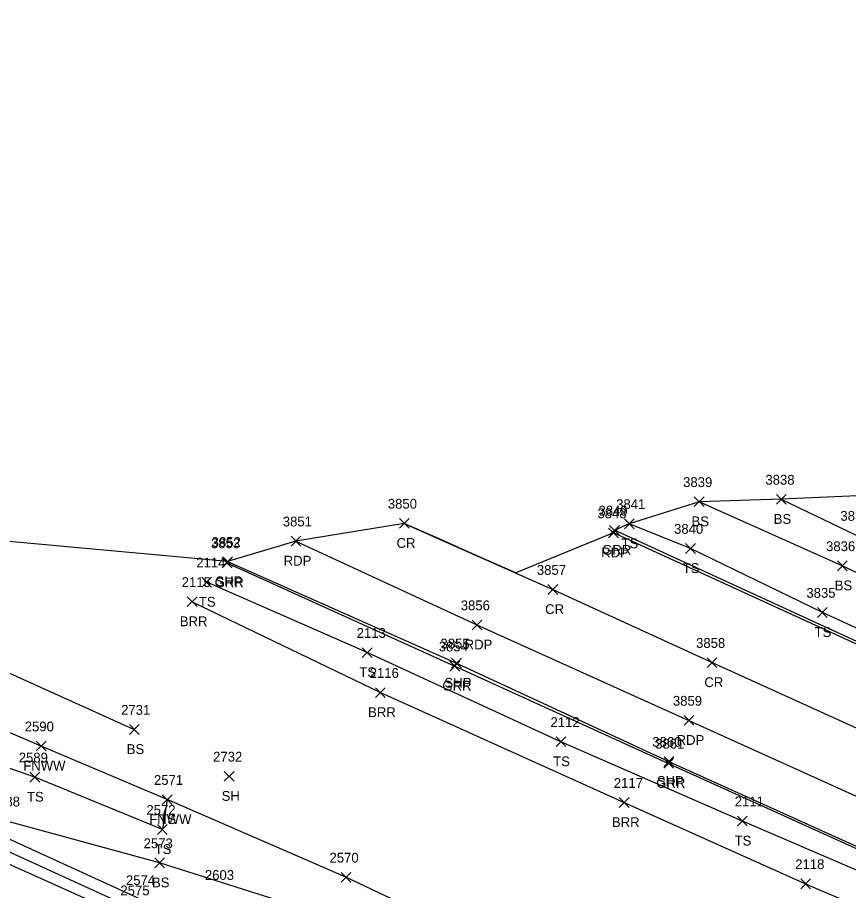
# Model space of a CAD drawing. Extents: x 1599569 to 1610055, y 642560 to 647860.
# Drawn here: x 1601133.3 to 1601302.9, y 647340.3 to 647518.5 of the extents above; entities that cross this region are included whole.
import ezdxf

# ---------------------------------------------------------------- set-up
doc = ezdxf.new("R2010")
doc.units = 0
for name, color, linetype in [('L_A', 7, 'Continuous'), ('L_I', 7, 'Continuous'), ('L_TIC', 7, 'Continuous'), ('LABL', 7, 'Continuous'), ('LELB', 7, 'Continuous'), ('LFNC', 7, 'Continuous'), ('LSOGP', 7, 'Continuous'), ('P_A', 7, 'Continuous'), ('P_I', 7, 'Continuous'), ('P_TIC', 7, 'Continuous'), ('PET', 7, 'Continuous'), ('PRC', 7, 'Continuous'), ('PSP', 7, 'Continuous'), ('R_A', 7, 'Continuous'), ('R_I', 7, 'Continuous'), ('R_TIC', 7, 'Continuous'), ('RGR', 7, 'Continuous'), ('RR', 7, 'Continuous'), ('S_I', 7, 'Continuous')]:
    doc.layers.add(name, color=color, linetype=linetype)

msp = doc.modelspace()

# ---------------------------------------------------------------- linework, layer by layer
at = {"layer": 'L_TIC'}
for points in [[(1601271.46, 647418.68), (1601273.46, 647420.68)], [(1601273.46, 647418.68), (1601271.46, 647420.68)], [(1601288.24, 647419.16), (1601290.24, 647421.16)], [(1601290.24, 647419.16), (1601288.24, 647421.16)], [(1601257.21, 647414.18), (1601259.21, 647416.18)], [(1601259.21, 647414.18), (1601257.21, 647416.18)], [(1601269.69, 647409.14), (1601271.69, 647411.14)], [(1601271.69, 647409.14), (1601269.69, 647411.14)], [(1601300.67, 647405.6), (1601302.67, 647407.6)], [(1601302.67, 647405.6), (1601300.67, 647407.6)], [(1601170.96, 647402.26), (1601172.96, 647404.26)], [(1601172.96, 647402.26), (1601170.96, 647404.26)], [(1601167.99, 647398.27), (1601169.99, 647400.27)], [(1601169.99, 647398.27), (1601167.99, 647400.27)], [(1601296.6, 647396.08), (1601298.6, 647398.08)], [(1601298.6, 647396.08), (1601296.6, 647398.08)], [(1601203.7, 647387.89), (1601205.7, 647389.89)], [(1601205.7, 647387.89), (1601203.7, 647389.89)], [(1601206.41, 647379.73), (1601208.41, 647381.73)], [(1601208.41, 647379.73), (1601206.41, 647381.73)], [(1601156.19, 647372.2), (1601158.19, 647374.2)], [(1601158.19, 647372.2), (1601156.19, 647374.2)], [(1601243.25, 647369.69), (1601245.25, 647371.69)], [(1601245.25, 647369.69), (1601243.25, 647371.69)], [(1601137.18, 647368.81), (1601139.18, 647370.81)], [(1601139.18, 647368.81), (1601137.18, 647370.81)], [(1601175.54, 647362.64), (1601177.54, 647364.64)], [(1601177.54, 647362.64), (1601175.54, 647364.64)], [(1601135.88, 647362.46), (1601137.88, 647364.46)], [(1601137.88, 647362.46), (1601135.88, 647364.46)], [(1601162.89, 647357.89), (1601164.89, 647359.89)], [(1601164.89, 647357.89), (1601162.89, 647359.89)], [(1601162.89, 647357.89), (1601164.89, 647359.89)], [(1601164.89, 647357.89), (1601162.89, 647359.89)], [(1601256.17, 647357.28), (1601258.17, 647359.28)], [(1601258.17, 647357.28), (1601256.17, 647359.28)], [(1601280.28, 647353.51), (1601282.28, 647355.51)], [(1601282.28, 647353.51), (1601280.28, 647355.51)], [(1601161.92, 647351.78), (1601163.92, 647353.78)], [(1601163.92, 647351.78), (1601161.92, 647353.78)], [(1601161.36, 647344.97), (1601163.36, 647346.97)], [(1601163.36, 647344.97), (1601161.36, 647346.97)], [(1601199.38, 647342.03), (1601201.38, 647344.03)], [(1601201.38, 647342.03), (1601199.38, 647344.03)], [(1601293.19, 647340.7), (1601295.19, 647342.7)], [(1601295.19, 647340.7), (1601293.19, 647342.7)]]:
    msp.add_lwpolyline(points, dxfattribs=at)
at = {"layer": 'LABL'}
msp.add_lwpolyline([(1601168.99, 647399.27), (1601207.41, 647380.73), (1601257.17, 647358.28), (1601294.19, 647341.7), (1601346.91, 647319.14), (1601374.73, 647304.92), (1601415.9, 647287.21), (1601447.46, 647269.36), (1601451.82, 647260.74), (1601445.32, 647247.33), (1601438.38, 647230.38)], dxfattribs=at)
at = {"layer": 'LELB'}
for points in [[(1601329.86, 647260.18), (1601292.61, 647278.06), (1601262.72, 647292.4), (1601226.59, 647308.21), (1601190.68, 647323.36), (1601158.75, 647338.43), (1601129.91, 647351.62), (1601096.68, 647366.43), (1601056.58, 647384.54), (1601012.74, 647404.18), (1600965.22, 647426.07), (1600914.49, 647448.77), (1600866.79, 647471.13), (1600821.34, 647492.23), (1600763.72, 647518.52)], [(1601329.08, 647258.95), (1601292.39, 647275.61), (1601261.46, 647289.71), (1601225.27, 647305.87), (1601190.14, 647321.67), (1601157.62, 647336.35), (1601128.98, 647349.36), (1601095.53, 647364.39), (1601055.96, 647382.57), (1601011.7, 647402.22), (1600964.35, 647423.93), (1600913.28, 647446.74), (1600865.78, 647468.67), (1600819.14, 647488.99), (1600762.95, 647515.26)], [(1601277.64, 647306.94), (1601247.91, 647313.96), (1601233.47, 647321.04), (1601196.65, 647335.07), (1601162.36, 647345.97), (1601131.17, 647354.49), (1601097.9, 647368.75), (1601057.17, 647386.63), (1601013.7, 647406.22), (1600966.1, 647427.78), (1600916.08, 647451.44), (1600867.43, 647472.68), (1600824.54, 647496.94)], [(1601163.89, 647358.89), (1601162.92, 647352.78), (1601136.88, 647363.46), (1601101.2, 647375.84), (1601058.43, 647390.08), (1601014.73, 647408.69), (1600966.71, 647430.59), (1600917.74, 647454.04), (1600870.28, 647476.33), (1600824.54, 647496.94)], [(1600923.02, 647485.83), (1600958.02, 647473.82), (1601000.93, 647451.94), (1601046.02, 647433.27), (1601084.8, 647415.84), (1601116.74, 647391.45), (1601157.19, 647373.2)], [(1601404.15, 647367.47), (1601371.11, 647382.8), (1601340.04, 647397.51), (1601304.55, 647412.79), (1601289.24, 647420.16)], [(1601401.43, 647361.74), (1601367.5, 647374.69), (1601335.03, 647390.68), (1601301.67, 647406.6), (1601272.46, 647419.68)], [(1601397.61, 647351.48), (1601365.05, 647366.71), (1601330.24, 647382.11), (1601297.6, 647397.08), (1601270.69, 647410.14), (1601258.21, 647415.18)], [(1601313.74, 647340.53), (1601281.28, 647354.51), (1601244.25, 647370.69), (1601204.7, 647388.89), (1601171.96, 647403.26)]]:
    msp.add_lwpolyline(points, dxfattribs=at)
at = {"layer": 'LFNC'}
msp.add_lwpolyline([(1601438.38, 647230.38), (1601406.08, 647246.23), (1601390.36, 647253.65), (1601325.07, 647284.52), (1601295.93, 647298.24), (1601277.64, 647306.94), (1601251.54, 647319.32), (1601236.24, 647326.06), (1601200.38, 647343.03), (1601163.89, 647358.89), (1601138.18, 647369.81), (1601105.25, 647383.87), (1601061.33, 647402.55), (1601021.95, 647420.15), (1600970.86, 647443.1), (1600923.39, 647465.04), (1600876.08, 647486.37)], dxfattribs=at)
at = {"layer": 'LSOGP'}
msp.add_lwpolyline([(1601329.63, 647421.95), (1601289.24, 647420.17), (1601272.46, 647419.67), (1601258.21, 647415.18), (1601255.18, 647413.85), (1601254.97, 647413.31), (1601235.02, 647405.14), (1601227.44, 647408.51), (1601219.86, 647411.89), (1601212.28, 647415.27), (1601190.18, 647411.64), (1601176.24, 647407.45), (1601084.8, 647415.84), (1601084.8, 647415.85), (1601046.02, 647433.27), (1601000.93, 647451.95), (1600958.02, 647473.82), (1600923.02, 647485.84), (1600876.08, 647486.37), (1600824.54, 647496.94), (1600763.73, 647518.52)], dxfattribs=at)
at = {"layer": 'P_TIC'}
for points in [[(1601211.28, 647414.26), (1601213.28, 647416.26)], [(1601213.28, 647414.26), (1601211.28, 647416.26)], [(1601189.18, 647410.64), (1601191.18, 647412.64)], [(1601191.18, 647410.64), (1601189.18, 647412.64)], [(1601253.97, 647412.31), (1601255.97, 647414.31)], [(1601255.97, 647412.31), (1601253.97, 647414.31)], [(1601175.24, 647406.45), (1601177.24, 647408.45)], [(1601177.24, 647406.45), (1601175.24, 647408.45)], [(1601241.6, 647400.76), (1601243.6, 647402.76)], [(1601243.6, 647400.76), (1601241.6, 647402.76)], [(1601226.12, 647393.53), (1601228.12, 647395.53)], [(1601228.12, 647393.53), (1601226.12, 647395.53)], [(1601221.94, 647385.72), (1601223.94, 647387.72)], [(1601223.94, 647385.72), (1601221.94, 647387.72)], [(1601274.09, 647385.85), (1601276.09, 647387.85)], [(1601276.09, 647385.85), (1601274.09, 647387.85)], [(1601269.37, 647374.05), (1601271.37, 647376.05)], [(1601271.37, 647374.05), (1601269.37, 647376.05)], [(1601265.29, 647365.67), (1601267.29, 647367.67)], [(1601267.29, 647365.67), (1601265.29, 647367.67)]]:
    msp.add_lwpolyline(points, dxfattribs=at)
at = {"layer": 'PET'}
for points in [[(1601396.17, 647348.54), (1601351.62, 647369.26), (1601306.84, 647389.58), (1601254.97, 647413.31)], [(1601190.18, 647411.64), (1601227.12, 647394.53), (1601270.37, 647375.05), (1601323.45, 647351.03)]]:
    msp.add_lwpolyline(points, dxfattribs=at)
at = {"layer": 'PRC'}
msp.add_lwpolyline([(1601212.28, 647415.26), (1601242.6, 647401.76), (1601275.09, 647386.85), (1601331.27, 647361.35)], dxfattribs=at)
at = {"layer": 'PSP'}
msp.add_lwpolyline([(1601176.24, 647407.45), (1601222.94, 647386.72), (1601266.29, 647366.67), (1601318.65, 647342.96)], dxfattribs=at)
at = {"layer": 'R_TIC'}
for points in [[(1601254.19, 647412.85), (1601256.19, 647414.85)], [(1601256.19, 647412.85), (1601254.19, 647414.85)], [(1601175.1, 647406.2), (1601177.1, 647408.2)], [(1601177.1, 647406.2), (1601175.1, 647408.2)], [(1601221.59, 647385.13), (1601223.59, 647387.13)], [(1601223.59, 647385.13), (1601221.59, 647387.13)], [(1601265.22, 647365.28), (1601267.22, 647367.28)], [(1601267.22, 647365.28), (1601265.22, 647367.28)]]:
    msp.add_lwpolyline(points, dxfattribs=at)
at = {"layer": 'RGR'}
for points in [[(1601396.58, 647349.23), (1601351.85, 647369.72), (1601307.17, 647390.02), (1601255.19, 647413.85)], [(1601176.1, 647407.2), (1601222.59, 647386.13), (1601266.22, 647366.28), (1601318.53, 647342.58)]]:
    msp.add_lwpolyline(points, dxfattribs=at)
at = {"layer": 'RR'}
msp.add_lwpolyline([(1601328.26, 647256.93), (1601292.48, 647273.14), (1601260.65, 647287.58), (1601223.96, 647303.96), (1601189.34, 647319.67), (1601156.57, 647334.47), (1601128.05, 647347.29), (1601094.57, 647362.49), (1601054.86, 647380.37), (1601010.55, 647400.2), (1600963.24, 647421.51), (1600912.09, 647444.53), (1600864.46, 647466.02), (1600817.98, 647486.96), (1600761.67, 647512.45)], dxfattribs=at)

# ---------------------------------------------------------------- texts
at = {"layer": 'L_A'}
for s, p in [('BS', (1601270.9, 647414.68)), ('BS', (1601287.68, 647415.16)), ('TS', (1601256.62, 647410.18)), ('TS', (1601269.1, 647405.14)), ('BS', (1601300.12, 647401.6)), ('TS', (1601170.37, 647398.26)), ('BRR', (1601166.48, 647394.27)), ('TS', (1601296.01, 647392.08)), ('TS', (1601203.11, 647383.89)), ('BRR', (1601204.9, 647375.73)), ('BS', (1601155.64, 647368.2)), ('FNWW', (1601134.53, 647364.81)), ('TS', (1601242.66, 647365.69)), ('TS', (1601135.29, 647358.46)), ('SH', (1601175.02, 647358.64)), ('FNWW', (1601160.24, 647353.89)), ('TS', (1601162.3, 647353.89)), ('BRR', (1601254.66, 647353.28)), ('TS', (1601279.69, 647349.51)), ('TS', (1601161.33, 647347.78)), ('BS', (1601160.8, 647340.97))]:
    msp.add_text(s, height=2, dxfattribs=at).set_placement(p)
at = {"layer": 'L_I'}
for s, p in [('3838', (1601285.98, 647423.16)), ('3839', (1601269.19, 647422.68)), ('3841', (1601255.52, 647418.18)), ('3837', (1601301.29, 647415.79)), ('3840', (1601267.34, 647413.14)), ('3836', (1601298.36, 647409.6)), ('2114', (1601169.83, 647406.26)), ('2115', (1601166.86, 647402.27)), ('3835', (1601294.34, 647400.08)), ('2113', (1601202.57, 647391.89)), ('2116', (1601205.23, 647383.73)), ('2731', (1601154.5, 647376.2)), ('2112', (1601242.12, 647373.69)), ('2590', (1601134.83, 647372.81)), ('2589', (1601133.61, 647366.46)), ('2732', (1601173.28, 647366.64)), ('2571', (1601161.2, 647361.89)), ('2571', (1601161.2, 647361.89)), ('2117', (1601255.05, 647361.28)), ('2588', (1601127.91, 647357.49)), ('2111', (1601279.72, 647357.51)), ('2572', (1601159.66, 647355.78)), ('2573', (1601159.1, 647348.97)), ('2570', (1601197.03, 647346.03)), ('2118', (1601292.07, 647344.7)), ('2574', (1601155.49, 647341.43)), ('2575', (1601154.36, 647339.35))]:
    msp.add_text(s, height=2, dxfattribs=at).set_placement(p)
at = {"layer": 'P_A'}
for s, p in [('CR', (1601210.71, 647410.26)), ('RDP', (1601252.46, 647408.31)), ('RDP', (1601187.67, 647406.64)), ('SHP', (1601173.77, 647402.45)), ('CR', (1601241.03, 647396.76)), ('RDP', (1601224.61, 647389.53)), ('SHP', (1601220.48, 647381.72)), ('CR', (1601273.52, 647381.85)), ('RDP', (1601267.86, 647370.05)), ('SHP', (1601263.83, 647361.67))]:
    msp.add_text(s, height=2, dxfattribs=at).set_placement(p)
at = {"layer": 'P_I'}
for s, p in [('3850', (1601208.93, 647418.26)), ('3848', (1601251.71, 647416.31)), ('3851', (1601187.49, 647414.64)), ('3852', (1601172.98, 647410.45)), ('3857', (1601239.34, 647404.76)), ('3856', (1601223.81, 647397.53)), ('3855', (1601219.68, 647389.72)), ('3858', (1601271.83, 647389.85)), ('3859', (1601267.1, 647378.05)), ('3860', (1601262.9, 647369.67))]:
    msp.add_text(s, height=2, dxfattribs=at).set_placement(p)
at = {"layer": 'R_A'}
for p in [(1601252.67, 647408.85), (1601173.59, 647402.2), (1601220.07, 647381.13), (1601263.7, 647361.28)]:
    msp.add_text('GRR', height=2, dxfattribs=at).set_placement(p)
at = {"layer": 'R_I'}
for s, p in [('3849', (1601251.92, 647416.85)), ('3853', (1601172.84, 647410.2)), ('3854', (1601219.33, 647389.13)), ('3861', (1601263.48, 647369.28))]:
    msp.add_text(s, height=2, dxfattribs=at).set_placement(p)
at = {"layer": 'S_I'}
msp.add_text('2603', height=2, dxfattribs=at).set_placement((1601171.6, 647342.49))

doc.saveas('drawing.dxf')
